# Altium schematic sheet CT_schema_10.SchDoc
size 403 x 220 mm
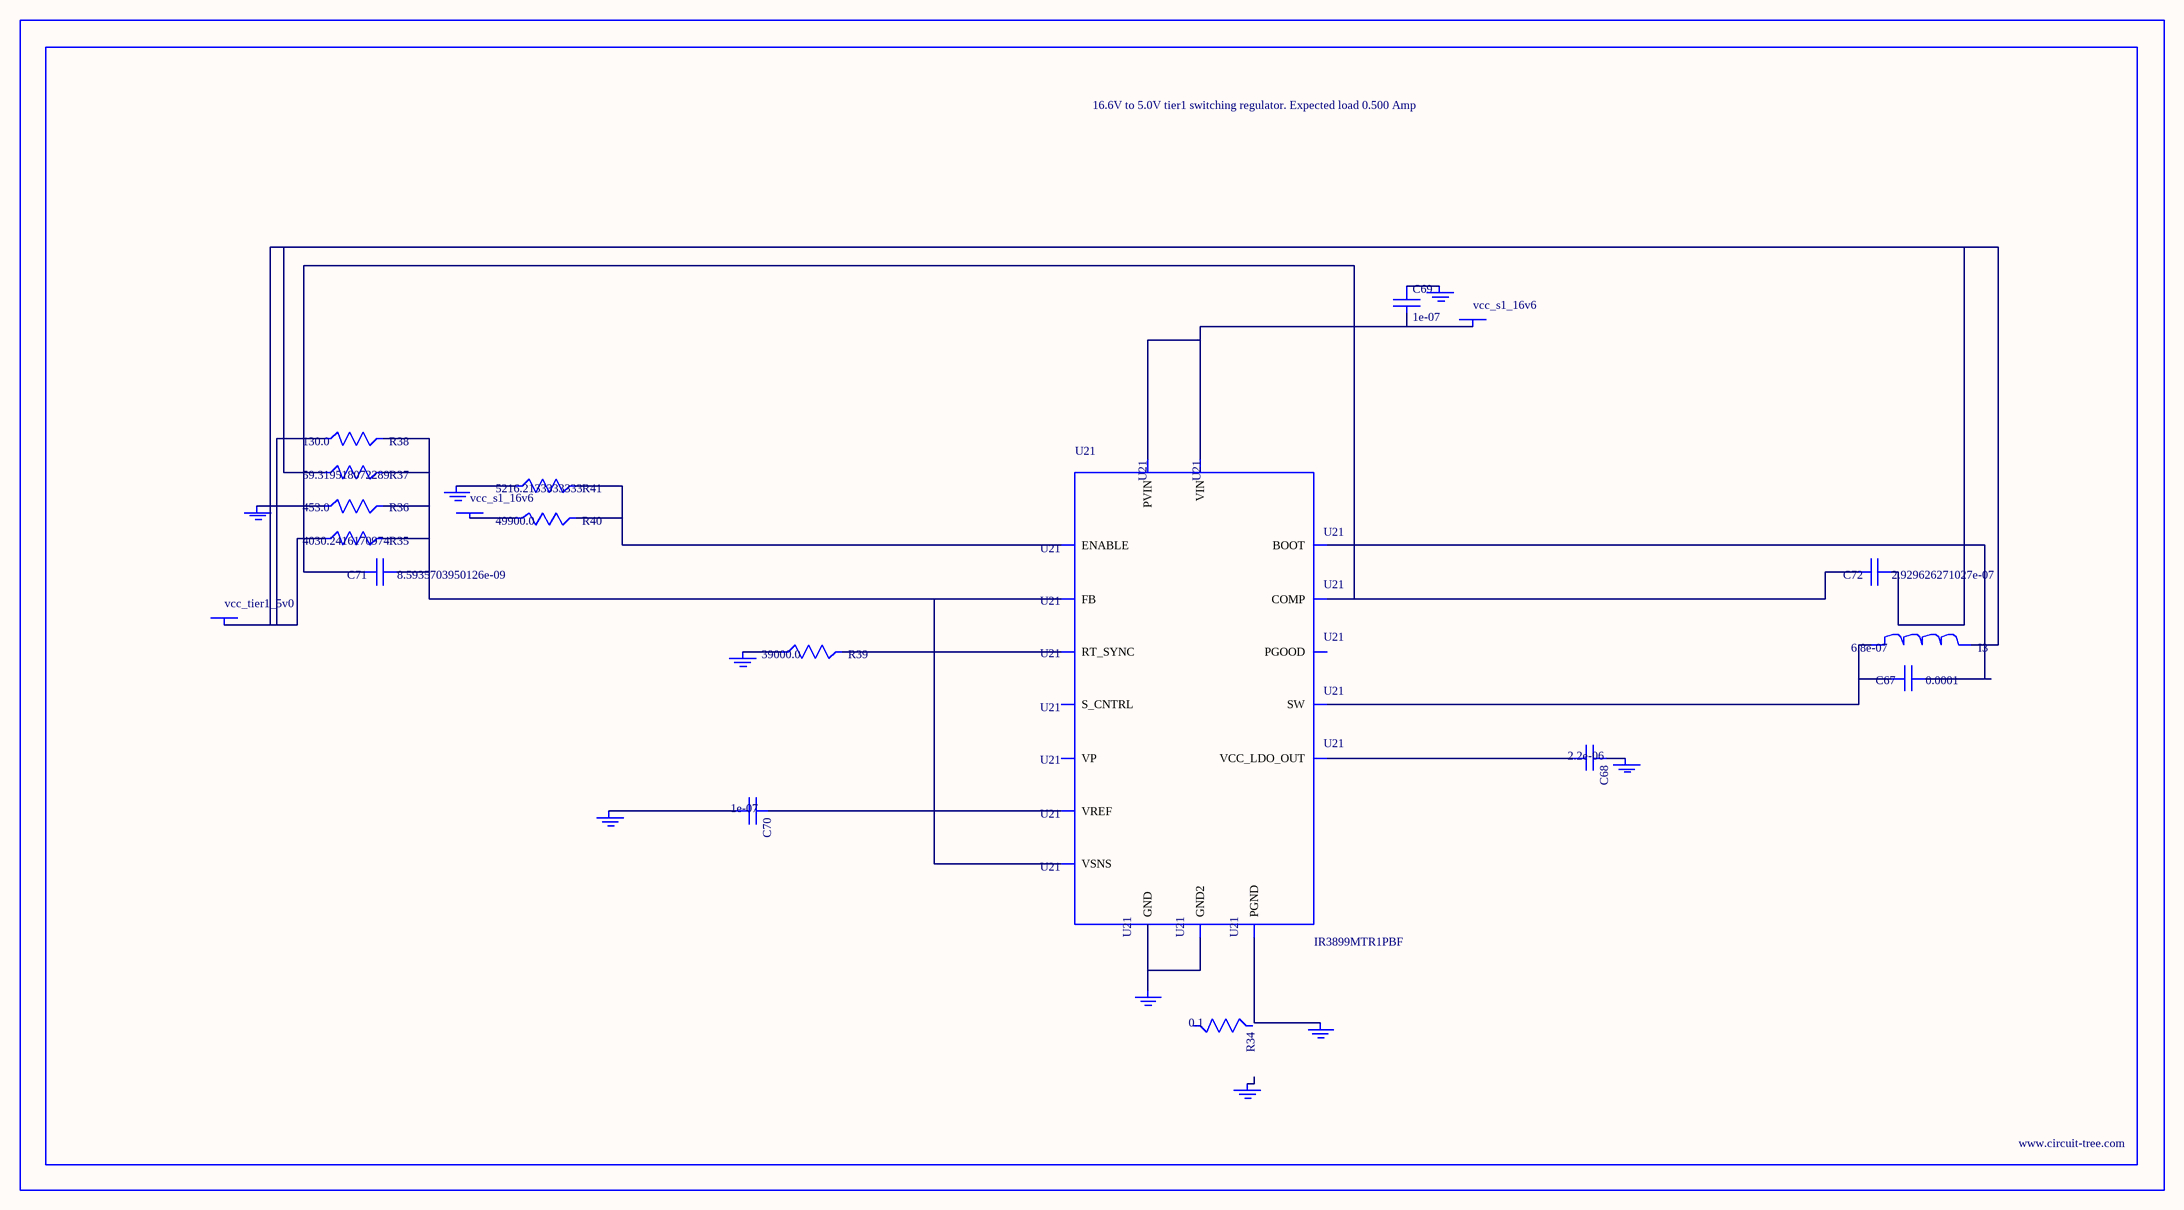
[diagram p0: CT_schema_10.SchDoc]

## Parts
BORDER9  (no value)
C67  0.0001  [C1210]
C68  2.2e-06  [C0603]
C69  1e-07  [C0402]
C70  1e-07  [C0402]
C71  8.5935703950126e-09  [R0603]
C72  2.929626271027e-07  [R0603]
GND_INSTANCE_9_0  (no value)
GND_INSTANCE_9_1  (no value)
GND_INSTANCE_9_2  (no value)
GND_INSTANCE_9_3  (no value)
GND_INSTANCE_9_4  (no value)
GND_INSTANCE_9_5  (no value)
GND_INSTANCE_9_6  (no value)
GND_INSTANCE_9_7  (no value)
GND_INSTANCE_9_8  (no value)
I3  6.8e-07  [IND25X25CZ]
POWER_INSTANCE_9_0  vcc_s1_16v6
POWER_INSTANCE_9_1  vcc_s1_16v6
POWER_INSTANCE_9_2  vcc_tier1_5v0
R34  0.1  [R0603]
R35  4030.2416170974  [R0603]
R36  453.0  [R0603]
R37  59.319518072289  [R0603]
R38  130.0  [R0603]
R39  39000.0  [R0603]
R40  49900.0  [R0603]
R41  5216.2133333333  [R0603]
U21  IR3899MTR1PBF  [IR3899MTR1PBF]

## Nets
NetC67_1: C67.1 U21.14(BOOT)
NetC67_2: C67.2 I3.1 U21.12(SW)
NetC68_1: C68.1 GND_INSTANCE_9_4.0(GND)
NetC68_2: C68.2 U21.10(VCC_LDO_OUT)
NetC69_1: C69.1 GND_INSTANCE_9_3.0(GND)
NetC69_2: C69.2 POWER_INSTANCE_9_0.0(PWR) U21.9(VIN) U21.13(PVIN)
NetC70_1: C70.1 U21.2(VREF)
NetC70_2: C70.2 GND_INSTANCE_9_1.0(GND)
NetC71_1: C71.1 R35.2 R36.2 R37.2 R38.2 U21.1(FB) U21.8(VSNS)
NetC71_2: C71.2 C72.2 U21.3(COMP)
NetC72_1: C72.1 I3.2 POWER_INSTANCE_9_2.0(PWR) R35.1 R37.1 R38.1
NetGND_INSTANCE_9_0_0: GND_INSTANCE_9_0.0(GND) R36.1
NetGND_INSTANCE_9_2_0: GND_INSTANCE_9_2.0(GND) R39.1
NetGND_INSTANCE_9_6_0: GND_INSTANCE_9_6.0(GND) U21.11(PGND)
NetGND_INSTANCE_9_7_0: GND_INSTANCE_9_7.0(GND) R41.1
NetGND_INSTANCE_9_8_0: GND_INSTANCE_9_8.0(GND) U21.4(GND) U21.17(GND2)
NetPOWER_INSTANCE_9_1_0: POWER_INSTANCE_9_1.0(PWR) R40.1
NetR39_2: R39.2 U21.5(RT_SYNC)
NetR40_2: R40.2 R41.2 U21.15(ENABLE)

Not connected (* = marked no-connect by the designer): GND_INSTANCE_9_5 0(GND); R34 1 2; U21 6(S_CNTRL) 7(PGOOD) 16(VP)

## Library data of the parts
BORDER9 = BORDER_PAGE9
C67 = GRM32ER61A107ME20L
C68 = C0603C225K8RACTU
C69 C70 = C0402C104K3RACTU
C71 = C71
C72 = C72
GND_INSTANCE_9_0-GND_INSTANCE_9_8 = GND
I3 = IHLP2525CZERR68M01
POWER_INSTANCE_9_0-POWER_INSTANCE_9_2 = PWR
R34 = ERJ-3RSFR10V
R35 = R35
R36 = ERJ-3EKF4530V
R37 = R37
R38 = RC0603JR-07130RL
R39 = RC0603JR-0739KL
R40 = RC0603FR-0749K9
R41 = R41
